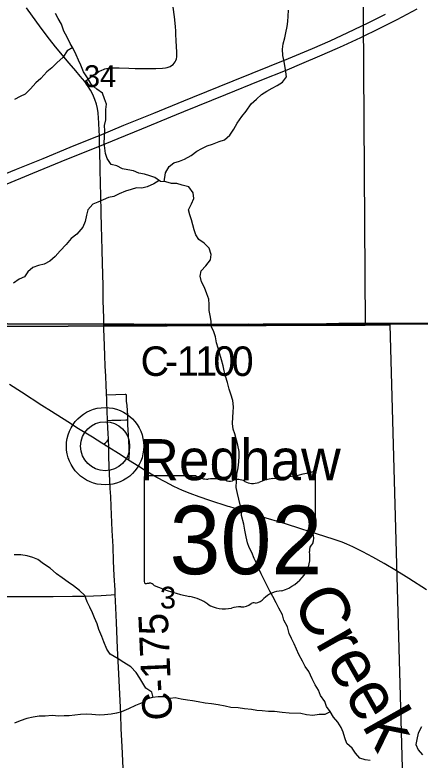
# Model space of a CAD drawing. Extents: x 0 to 34, y 0 to 22.
# Drawn here: x 6.453 to 7.232, y 16.027 to 17.462 of the extents above; entities that cross this region are included whole.
import ezdxf

# ---------------------------------------------------------------- set-up
doc = ezdxf.new("R2010")
doc.units = 0
for name, color, linetype in [('GM_X_County_Road', 7, 'Continuous'), ('GM_X_County_Road_Text', 7, 'Continuous'), ('GM_X_Interstate_Route', 7, 'Continuous'), ('GM_X_Minor_River', 7, 'Continuous'), ('GM_X_Minor_River_Text', 7, 'Continuous'), ('GM_X_Section', 7, 'Continuous'), ('GM_X_Section_Text', 7, 'Continuous'), ('GM_X_State_Location', 7, 'Continuous'), ('GM_X_State_Route', 7, 'Continuous'), ('GM_X_State_Shield', 7, 'Continuous'), ('GM_X_Township_Road', 7, 'Continuous'), ('GM_X_Unincorporated', 7, 'Continuous'), ('GM_X_Unincorporated_Location', 7, 'Continuous'), ('GM_X_Unincorporated_Text', 7, 'Continuous')]:
    doc.layers.add(name, color=color, linetype=linetype)

msp = doc.modelspace()

# ---------------------------------------------------------------- linework, layer by layer
at = {"layer": 'GM_X_County_Road'}
msp.add_line((6.6333, 16.6292), (6.633, 16.6443), dxfattribs=at)
for points in [[(6.5871, 17.3339), (6.5784, 17.3443), (6.5702, 17.3543), (6.5574, 17.3689), (6.5308, 17.4005), (6.5192, 17.415), (6.5035, 17.4366), (6.4752, 17.4757)], [(6.624, 16.866), (6.6235, 16.8783), (6.6227, 16.912), (6.6223, 16.9408), (6.6211, 16.9843), (6.6208, 17.0091), (6.6201, 17.0337), (6.6195, 17.0552), (6.6187, 17.08), (6.6179, 17.1165), (6.6175, 17.1354), (6.6166, 17.1662), (6.6159, 17.2001), (6.6157, 17.2094), (6.6152, 17.2199), (6.6152, 17.23), (6.6149, 17.239), (6.6143, 17.2539), (6.6138, 17.2631), (6.6128, 17.2734), (6.6114, 17.2819), (6.6095, 17.29), (6.6062, 17.2993), (6.6024, 17.3087), (6.598, 17.3168), (6.5935, 17.3244), (6.5905, 17.3289), (6.5871, 17.3339)], [(6.6291, 16.7298), (6.6289, 16.7353), (6.6282, 16.7484), (6.6275, 16.7667), (6.6266, 16.7856), (6.6258, 16.8061), (6.6242, 16.8428), (6.6238, 16.8566), (6.624, 16.866)], [(6.624, 16.866), (6.6605, 16.8658), (6.6752, 16.8648), (6.7021, 16.8645), (6.7162, 16.8646), (6.7435, 16.8645), (6.7647, 16.8641), (6.7874, 16.8639), (6.8225, 16.8643), (6.8596, 16.8645), (6.8731, 16.8647), (6.8851, 16.8649), (6.9027, 16.865), (6.9159, 16.865), (6.9306, 16.8652), (6.9501, 16.8653), (6.9811, 16.8655), (7.0527, 16.866), (7.0765, 16.8662), (7.1103, 16.8665), (7.1366, 16.8673), (7.1607, 16.8673), (7.1965, 16.8673), (7.2265, 16.8672), (7.2647, 16.8669)], [(6.6309, 16.6812), (6.6303, 16.7007), (6.6298, 16.7159), (6.6293, 16.7254), (6.6291, 16.7298)], [(6.633, 16.6443), (6.6322, 16.6575), (6.6317, 16.666), (6.6309, 16.6812)], [(6.6229, 16.6357), (6.6267, 16.6384), (6.6287, 16.6399), (6.6304, 16.6416), (6.633, 16.6443)], [(6.6458, 16.3461), (6.6453, 16.3546), (6.6438, 16.3825), (6.6426, 16.4104), (6.6416, 16.4384), (6.6401, 16.4694), (6.638, 16.5159), (6.637, 16.5346), (6.6362, 16.5501), (6.6343, 16.5935), (6.6337, 16.612), (6.6334, 16.6244), (6.6333, 16.6292)], [(6.6699, 15.777), (6.6687, 15.8332), (6.6672, 15.886), (6.6652, 15.9264), (6.6632, 15.9698), (6.6589, 16.0536), (6.6574, 16.0877), (6.6562, 16.1156), (6.6525, 16.1932), (6.6504, 16.2429), (6.6481, 16.2925), (6.6469, 16.3205), (6.6458, 16.3461)]]:
    msp.add_lwpolyline(points, dxfattribs=at)
at = {"layer": 'GM_X_Interstate_Route'}
for points in [[(6.3721, 17.1101), (6.4871, 17.1571), (6.5418, 17.1795), (6.5908, 17.1993), (6.6157, 17.2094), (6.6512, 17.2239), (6.6972, 17.2428), (6.7633, 17.2699), (6.778, 17.2758), (6.8583, 17.3084), (6.9245, 17.3355), (6.9763, 17.3564), (7.005, 17.3683), (7.0392, 17.383), (7.0734, 17.3979), (7.0847, 17.4029), (7.1184, 17.4187), (7.1547, 17.4365), (7.1879, 17.4533), (7.2264, 17.4736)], [(6.3865, 17.1365), (6.4555, 17.1648), (6.5073, 17.1858), (6.5591, 17.207), (6.6051, 17.2258), (6.6152, 17.23), (6.6626, 17.2494), (6.7202, 17.2729), (6.7779, 17.2964), (6.7949, 17.3033), (6.8726, 17.335), (6.9791, 17.3781), (7.025, 17.3974), (7.0592, 17.4123), (7.0931, 17.4278), (7.1323, 17.4466), (7.1658, 17.4632)], [(6.2524, 16.8681), (6.6238, 16.8666), (6.6603, 16.8664), (6.6818, 16.8663), (6.7019, 16.8659), (6.7159, 16.8659), (6.7434, 16.8663), (6.7644, 16.8659), (6.7872, 16.8659), (6.8223, 16.8666), (6.8594, 16.8662), (6.8718, 16.8659), (6.8849, 16.8662), (6.9026, 16.8666), (6.9156, 16.8662), (6.9303, 16.8666), (6.9501, 16.8669), (6.9812, 16.8669), (7.0524, 16.8672), (7.0762, 16.8676), (7.11, 16.8679), (7.1364, 16.8679), (7.1605, 16.8679), (7.1963, 16.8679), (7.2264, 16.8682), (7.2645, 16.8679)], [(7.2645, 16.8679), (7.2264, 16.8682), (7.1963, 16.8679), (7.1605, 16.8679), (7.1364, 16.8679), (7.11, 16.8679), (7.0762, 16.8676), (7.0524, 16.8672), (6.9812, 16.8669), (6.9501, 16.8669), (6.9303, 16.8666), (6.9156, 16.8662), (6.9026, 16.8666), (6.8849, 16.8662), (6.8718, 16.8659), (6.8594, 16.8662), (6.8223, 16.8666), (6.7872, 16.8659), (6.7644, 16.8659), (6.7434, 16.8663), (6.7159, 16.8659), (6.7019, 16.8659), (6.6818, 16.8663), (6.6603, 16.8664), (6.6238, 16.8666), (6.2524, 16.8681)]]:
    msp.add_lwpolyline(points, dxfattribs=at)
at = {"layer": 'GM_X_Minor_River'}
for points in [[(6.8263, 17.0128), (6.8166, 17.0223), (6.8068, 17.0293), (6.8008, 17.0388), (6.7979, 17.0483), (6.7949, 17.0578), (6.7927, 17.0673), (6.7894, 17.0769), (6.7868, 17.0868), (6.7922, 17.0985), (6.7969, 17.1087), (6.7958, 17.1197), (6.7872, 17.1308), (6.7747, 17.1343), (6.7642, 17.1374), (6.7543, 17.1375), (6.7434, 17.1403), (6.7331, 17.1412), (6.7222, 17.1489), (6.7124, 17.152), (6.7018, 17.1555), (6.6912, 17.1575), (6.6807, 17.1618), (6.6701, 17.1638), (6.6599, 17.1658), (6.649, 17.1716), (6.638, 17.174), (6.6301, 17.1854), (6.6268, 17.1953), (6.6258, 17.2056), (6.6243, 17.2155), (6.6252, 17.2264), (6.626, 17.2386), (6.6254, 17.2492), (6.6277, 17.2602), (6.6279, 17.2799), (6.6288, 17.2898), (6.6254, 17.3001), (6.621, 17.3111), (6.6101, 17.3188), (6.5995, 17.3288), (6.5921, 17.341), (6.5846, 17.3524), (6.5798, 17.365), (6.575, 17.3749), (6.5705, 17.3852), (6.5649, 17.397), (6.5593, 17.4069), (6.553, 17.4188), (6.547, 17.4306), (6.5422, 17.4439), (6.5362, 17.455), (6.531, 17.4645)], [(6.7402, 17.1406), (6.7427, 17.1578), (6.7493, 17.1702), (6.7588, 17.177), (6.7691, 17.1803), (6.7793, 17.184), (6.7919, 17.1911), (6.8026, 17.1997), (6.8124, 17.2045), (6.8227, 17.2097), (6.833, 17.2134), (6.8455, 17.2182), (6.8561, 17.2215), (6.8664, 17.2302), (6.8737, 17.2422), (6.8803, 17.2536), (6.8891, 17.2664), (6.8979, 17.2769), (6.9071, 17.2905), (6.9174, 17.2995), (6.9273, 17.3089), (6.9376, 17.3152), (6.9478, 17.3208), (6.9574, 17.326), (6.9676, 17.3324), (6.9753, 17.3429), (6.9742, 17.3524), (6.9706, 17.3722), (6.9681, 17.3836), (6.9674, 17.3961), (6.9686, 17.406), (6.9721, 17.4177), (6.9737, 17.4276), (6.9765, 17.4393), (6.9777, 17.4495), (6.9786, 17.4594), (6.979, 17.4712)], [(6.5639, 17.3989), (6.5535, 17.3926), (6.5447, 17.3802), (6.534, 17.37), (6.5237, 17.3602), (6.5142, 17.3524), (6.5027, 17.3396), (6.4932, 17.3313), (6.4828, 17.3197), (6.4725, 17.3095), (6.463, 17.3051), (6.452, 17.2991)], [(6.7302, 17.1433), (6.7198, 17.1367), (6.7073, 17.1312), (6.6971, 17.1282), (6.6865, 17.1291), (6.6766, 17.1258), (6.6652, 17.1228), (6.653, 17.1173), (6.6428, 17.1121), (6.6329, 17.1103), (6.6223, 17.1062), (6.6124, 17.1017), (6.6025, 17.0977), (6.5933, 17.0867), (6.5906, 17.0761), (6.5882, 17.064), (6.5832, 17.0534), (6.5721, 17.0399), (6.5611, 17.0317), (6.5515, 17.02), (6.54, 17.008), (6.5301, 16.997), (6.5198, 16.9877), (6.5088, 16.9821), (6.4978, 16.9795), (6.4871, 16.9758), (6.4776, 16.9676), (6.4711, 16.9578), (6.4612, 16.9533), (6.4501, 16.9458)], [(7.1364, 16.0266), (7.1266, 16.0282), (7.1164, 16.0309), (7.1077, 16.0405), (7.1018, 16.0504), (7.0916, 16.0596), (7.0876, 16.0703), (7.0842, 16.081), (7.0802, 16.0905), (7.0742, 16.1004), (7.0659, 16.11), (7.0592, 16.121), (7.0525, 16.1306), (7.0488, 16.1405), (7.0409, 16.152), (7.0368, 16.1622), (7.0301, 16.1722), (7.0249, 16.184), (7.0182, 16.1977), (7.0111, 16.2076), (7.0063, 16.2176), (6.9988, 16.2305), (6.9943, 16.2412), (6.9903, 16.2511), (6.9847, 16.2614), (6.9806, 16.2709), (6.9773, 16.2839), (6.9702, 16.2968), (6.9676, 16.3071), (6.9606, 16.3201), (6.9553, 16.3304), (6.949, 16.3422), (6.9434, 16.3529), (6.9378, 16.3632), (6.9267, 16.3861), (6.9222, 16.3956), (6.9181, 16.4055), (6.9129, 16.4154), (6.9088, 16.4268), (6.9036, 16.4364), (6.9003, 16.4459), (6.8977, 16.4573), (6.8952, 16.4702), (6.8934, 16.4816), (6.8886, 16.4984), (6.8891, 16.5094), (6.8861, 16.5189), (6.8836, 16.5299), (6.881, 16.5406), (6.8781, 16.552), (6.8793, 16.5649), (6.8794, 16.5781), (6.8822, 16.5903), (6.8838, 16.6016), (6.8843, 16.6122), (6.884, 16.6217), (6.8814, 16.6335), (6.8789, 16.643), (6.8759, 16.6552), (6.8726, 16.6647), (6.8716, 16.6757), (6.872, 16.6875), (6.8729, 16.6974), (6.8733, 16.7076), (6.8723, 16.7197), (6.8683, 16.7319), (6.8649, 16.7414), (6.862, 16.7544), (6.8579, 16.7662), (6.8554, 16.7768), (6.8532, 16.7863), (6.8499, 16.7981), (6.8469, 16.8088), (6.844, 16.8206), (6.8407, 16.8305), (6.8385, 16.8423), (6.8352, 16.8518), (6.8311, 16.8613), (6.8304, 16.8723), (6.8283, 16.8833), (6.8265, 16.8932), (6.8262, 16.9042), (6.8259, 16.9149), (6.8222, 16.9251), (6.8174, 16.9369), (6.8118, 16.948), (6.8092, 16.9587), (6.8108, 16.9693), (6.82, 16.979), (6.8288, 16.9907), (6.83, 17.001), (6.8263, 17.0128)], [(6.7185, 16.148), (6.7161, 16.1585), (6.7044, 16.1659), (6.6988, 16.1754), (6.6928, 16.1849), (6.6861, 16.1964), (6.6756, 16.2067), (6.6624, 16.2152), (6.6515, 16.2222), (6.636, 16.2314), (6.6297, 16.2413), (6.6241, 16.2551), (6.6201, 16.2653), (6.6141, 16.2791), (6.6108, 16.2897), (6.6056, 16.3015), (6.6023, 16.311), (6.5971, 16.3221), (6.5918, 16.3324), (6.5874, 16.3442), (6.5773, 16.3542), (6.5656, 16.3626), (6.5551, 16.3699), (6.5438, 16.378), (6.5328, 16.3857), (6.5204, 16.3968), (6.508, 16.4053), (6.4971, 16.4134), (6.4873, 16.4177), (6.476, 16.4204), (6.4639, 16.4224), (6.4514, 16.4226)], [(7.0595, 16.1205), (7.0489, 16.1155), (7.0383, 16.1152), (7.0262, 16.1134), (7.0137, 16.1143), (7.0031, 16.117), (6.9804, 16.118), (6.9672, 16.1193), (6.952, 16.1213), (6.9403, 16.1211), (6.9286, 16.1223), (6.9184, 16.1232), (6.9082, 16.1248), (6.8945, 16.1261), (6.8821, 16.1281), (6.8684, 16.129), (6.8575, 16.1314), (6.8439, 16.1341), (6.831, 16.1358), (6.8185, 16.137), (6.8053, 16.1398), (6.7947, 16.1415), (6.7845, 16.1427), (6.7728, 16.1447), (6.761, 16.1471), (6.7516, 16.146), (6.7395, 16.1492), (6.7285, 16.1493), (6.7175, 16.1479), (6.708, 16.1453), (6.6974, 16.1375), (6.6848, 16.1323), (6.6715, 16.126), (6.6578, 16.1204), (6.648, 16.1175), (6.6377, 16.1157), (6.6252, 16.1143), (6.615, 16.114), (6.601, 16.1153), (6.59, 16.1161), (6.579, 16.1155), (6.568, 16.1137), (6.5574, 16.1127), (6.5472, 16.1128), (6.5373, 16.1121), (6.5245, 16.113), (6.5112, 16.112), (6.4991, 16.1121), (6.4877, 16.1103), (6.4756, 16.1078), (6.4631, 16.1033), (6.452, 16.0985)], [(7.235, 16.0916), (7.2285, 16.0792), (7.2257, 16.0671), (7.2238, 16.0572), (7.2286, 16.0473), (7.2372, 16.0377)]]:
    msp.add_lwpolyline(points, dxfattribs=at)
at = {"layer": 'GM_X_Section'}
for points in [[(7.1203, 17.8521), (7.1264, 16.8648), (6.1739, 16.8615), (6.1193, 16.8628), (6.1027, 17.8448)], [(7.1741, 16.8653), (7.2023, 15.8508), (6.6641, 15.8573), (6.2093, 15.844), (6.1739, 16.8615), (7.1264, 16.8648)]]:
    msp.add_lwpolyline(points, close=True, dxfattribs=at)
at = {"layer": 'GM_X_State_Route'}
for points in [[(6.8633, 16.5159), (6.8276, 16.5272), (6.8071, 16.5341), (6.7896, 16.5407), (6.7753, 16.5466), (6.7584, 16.5544), (6.7418, 16.5628), (6.7255, 16.5717), (6.7041, 16.5842), (6.6909, 16.5923), (6.6715, 16.605), (6.6649, 16.6092), (6.6517, 16.6175), (6.6333, 16.6292), (6.6229, 16.6357), (6.6202, 16.6374), (6.6017, 16.649), (6.5753, 16.6653), (6.5543, 16.6785), (6.523, 16.6986), (6.5046, 16.7102), (6.4656, 16.7355), (6.442, 16.7504)], [(6.9189, 16.4987), (6.8914, 16.5072), (6.8662, 16.515), (6.8633, 16.5159)], [(7.2448, 16.3551), (7.2109, 16.3771), (7.1871, 16.3918), (7.1631, 16.4062), (7.1414, 16.4184), (7.1222, 16.4286), (7.1026, 16.4383), (7.0912, 16.4433), (7.0825, 16.4467), (7.0648, 16.4528), (7.0352, 16.4621), (7.0027, 16.4726), (6.9731, 16.4822), (6.9255, 16.4966), (6.9189, 16.4987)]]:
    msp.add_lwpolyline(points, dxfattribs=at)
at = {"layer": 'GM_X_State_Shield'}
for p, q in [((6.7012, 16.5713), (6.7012, 16.3711)), ((6.801, 16.5747), (6.7044, 16.5747)), ((7.0308, 16.475), (7.0308, 16.5797)), ((7.0307, 16.475), (7.0308, 16.475))]:
    msp.add_line(p, q, dxfattribs=at)
for centre, major_axis, start_param, end_param in [((6.9134, 16.8475), (0.3495, 0), 4.814394, 5.042369), ((7.0271, 16.5801), (0.00367, 0), 6.141152, 7.989035), ((6.705, 16.5717), (0.00382, 0), 1.712693, 3.28349), ((6.8239, 16.5979), (0.037, 0), 4.042523, 4.731795), ((6.8362, 16.4624), (0.133, 0), 1.404758, 1.657858), ((6.8821, 16.5496), (0.0222, 0), 0.950623, 2.079405), ((6.958, 16.5136), (0.0703, 0), 1.699011, 2.107814), ((6.8664, 16.5727), (0.0107, 0), 3.836095, 5.185415), ((6.9108, 16.5813), (0.0267, 0), 4.081561, 5.145723), ((7.0299, 16.4673), (0.00568, 0), 1.883978, 3.671073), ((7.0269, 16.4746), (0.00393, 0), 5.05454, 6.418171), ((6.9938, 16.4541), (0.0341, 0), 5.934695, 6.695948), ((7.0439, 16.4312), (0.0248, 0), 2.387724, 3.262537), ((6.933, 16.4179), (0.0874, 0), 5.101752, 6.440018), ((6.705, 16.3707), (0.00385, 0), 3.00124, 4.508301), ((6.7056, 16.3912), (0.0294, 0), 4.665946, 4.897461), ((6.7116, 16.3596), (0.0106, 0), 0.519207, 1.627899), ((6.8454, 16.5394), (0.2524, 0), 4.195997, 4.488961), ((6.9698, 16.315), (0.0479, 0), 1.647645, 2.488434), ((6.7702, 16.2812), (0.079, 0), 0.823519, 1.323587), ((6.8556, 16.3586), (0.0501, 0), 4.026481, 4.996735), ((6.8882, 16.3436), (0.0267, 0), 4.691044, 5.507374), ((6.9124, 16.3242), (0.00752, 0), 1.147584, 2.315152), ((6.9092, 16.3518), (0.0282, 0), 4.937069, 5.64225), ((6.8845, 16.2894), (0.0412, 0), 1.495662, 1.94098)]:
    msp.add_ellipse(centre, major_axis=major_axis, ratio=0.8, start_param=start_param, end_param=end_param, dxfattribs=at)
at = {"layer": 'GM_X_Township_Road'}
for points in [[(6.5871, 17.3339), (6.5915, 17.3371), (6.5974, 17.3416), (6.6142, 17.3528), (6.6201, 17.3558), (6.6231, 17.357), (6.6258, 17.3578), (6.6288, 17.3585), (6.6314, 17.359), (6.6344, 17.3595), (6.6409, 17.3599), (6.6532, 17.36), (6.6718, 17.3594), (6.6842, 17.3589), (6.6903, 17.3589), (6.6933, 17.3589), (6.7145, 17.3589), (6.7238, 17.3589), (6.7364, 17.3595), (6.7427, 17.3601), (6.7459, 17.3607), (6.7492, 17.3617), (6.7516, 17.3626), (6.7543, 17.3644), (6.7571, 17.3664), (6.7592, 17.3689), (6.761, 17.3716), (6.7624, 17.3743), (6.7634, 17.3772), (6.764, 17.3809), (6.7642, 17.3844), (6.7642, 17.3904), (6.7632, 17.4122), (6.7626, 17.4246), (6.7625, 17.4276), (6.7623, 17.4307), (6.7615, 17.4397), (6.7597, 17.4582), (6.7575, 17.4765)], [(6.6699, 16.6823), (6.6697, 16.6905), (6.6686, 16.7102), (6.6675, 16.7185), (6.6675, 16.7288), (6.6675, 16.7297), (6.6672, 16.7305), (6.6663, 16.7312), (6.665, 16.7315), (6.6291, 16.7298)], [(6.6309, 16.6812), (6.6392, 16.6815), (6.6482, 16.6817), (6.6565, 16.6819), (6.6663, 16.6822), (6.6699, 16.6823)], [(6.6715, 16.605), (6.6723, 16.6095), (6.6726, 16.6125), (6.673, 16.6175), (6.6728, 16.6232), (6.6727, 16.6296), (6.6722, 16.6407), (6.6715, 16.6527), (6.6707, 16.6629), (6.6701, 16.6728), (6.6699, 16.6823)], [(6.2129, 16.3421), (6.25, 16.3421), (6.2748, 16.3418), (6.2934, 16.3417), (6.3276, 16.3418), (6.3586, 16.3421), (6.3959, 16.3423), (6.4301, 16.3424), (6.4798, 16.3425), (6.4953, 16.3425), (6.5263, 16.3427), (6.5635, 16.343), (6.5852, 16.3431), (6.6041, 16.3437), (6.6186, 16.3441), (6.628, 16.3447), (6.6376, 16.3455), (6.6458, 16.3461)]]:
    msp.add_lwpolyline(points, dxfattribs=at)
at = {"layer": 'GM_X_Unincorporated'}
for radius in [0.0744, 0.0472]:
    msp.add_circle((6.6262, 16.6317), radius, dxfattribs=at)
at = {"layer": 'GM_X_Unincorporated_Location'}
msp.add_line((6.6262, 16.6317), (6.6262, 16.6317), dxfattribs=at)

# ---------------------------------------------------------------- texts
at = {"layer": 'GM_X_County_Road_Text'}
for s, height, rotation, p in [('C', 0.0568, 0.363, (6.6947, 16.7668)), ('1', 0.0568, 0.203, (6.7646, 16.7672)), ('1', 0.0568, 359.9896, (6.7996, 16.7673)), ('0', 0.0568, 359.6982, (6.8345, 16.7673)), ('0', 0.0568, 359.4744, (6.8695, 16.7671)), ('-', 0.0568, 0.3122, (6.7413, 16.7671)), ('C-175', 0.05682, 92.4776, (6.7557, 16.1049))]:
    msp.add_text(s, height=height, rotation=rotation, dxfattribs=at).set_placement(p)
at = {"layer": 'GM_X_Minor_River_Text'}
msp.add_text('Creek', height=0.09473, rotation=299.4952, dxfattribs=at).set_placement((6.9844, 16.3329))
at = {"layer": 'GM_X_Section_Text'}
for s, height, p in [('34', 0.04186, (6.5854, 17.3231)), ('3', 0.0419, (6.7317, 16.3193))]:
    msp.add_text(s, height=height, rotation=0, dxfattribs=at).set_placement(p)
at = {"layer": 'GM_X_State_Location'}
for s in ['s', 'r']:
    msp.add_text(s, height=0.000189, dxfattribs=at).set_placement((6.8623, 16.4579))
msp.add_text('302', height=0.000189, rotation=0, dxfattribs=at).set_placement((6.7954, 16.4441))
at = {"layer": 'GM_X_State_Shield'}
msp.add_text('302', height=0.13184, dxfattribs=at).set_placement((6.7502, 16.3853))
at = {"layer": 'GM_X_Unincorporated_Text'}
msp.add_text('Redhaw', height=0.07898, rotation=0, dxfattribs=at).set_placement((6.6921, 16.5663))

doc.saveas('drawing.dxf')
